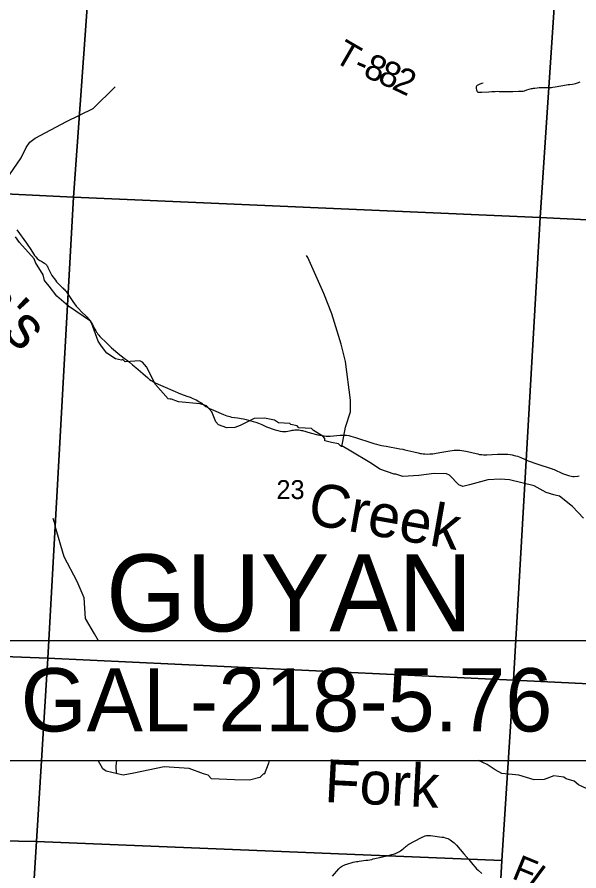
# Model space of a CAD drawing. Extents: x -2.1 to 31.9, y 6.3 to 28.3.
# Drawn here: x 1.321 to 2.564, y 23.525 to 25.414 of the extents above; entities that cross this region are included whole.
import ezdxf

# ---------------------------------------------------------------- set-up
doc = ezdxf.new("R2010")
doc.units = 0
for name, color, linetype in [('GM_X_County_Road', 7, 'Continuous'), ('GM_X_Minor_River', 7, 'Continuous'), ('GM_X_Minor_River_Text', 7, 'Continuous'), ('GM_X_Section', 7, 'Continuous'), ('GM_X_Section_Text', 7, 'Continuous'), ('GM_X_Township_Road', 7, 'Continuous'), ('GM_X_Township_Road_Text', 7, 'Continuous'), ('GM_X_Township_Text', 7, 'Continuous'), ('TX_P_1', 7, 'Continuous')]:
    doc.layers.add(name, color=color, linetype=linetype)

msp = doc.modelspace()

# ---------------------------------------------------------------- linework, layer by layer
at = {"layer": 'GM_X_County_Road'}
for points in [[(1.3205, 24.9435), (1.3263, 24.9353), (1.3361, 24.9224), (1.3423, 24.9139), (1.3465, 24.9078), (1.3488, 24.9043), (1.3513, 24.9004), (1.3572, 24.8904), (1.3596, 24.8868), (1.3624, 24.8835), (1.3654, 24.8805), (1.3693, 24.8775), (1.3718, 24.876)], [(1.3718, 24.876), (1.3735, 24.8749), (1.3783, 24.8721), (1.3818, 24.8698), (1.3832, 24.8687), (1.3845, 24.8677), (1.386, 24.8663), (1.3871, 24.8649), (1.3881, 24.8633), (1.3889, 24.8618), (1.3895, 24.8603), (1.3902, 24.8588), (1.3948, 24.8483), (1.3964, 24.8454), (1.3984, 24.8422), (1.4061, 24.8319), (1.4087, 24.8288), (1.4119, 24.8252), (1.4189, 24.8183), (1.421, 24.8162), (1.4228, 24.8145), (1.4248, 24.8125), (1.4267, 24.8105), (1.4282, 24.8087), (1.4298, 24.8068), (1.4314, 24.8047), (1.433, 24.8024), (1.4386, 24.7936), (1.4443, 24.785), (1.4522, 24.7748), (1.4543, 24.7722), (1.457, 24.7693), (1.4637, 24.7622), (1.474, 24.7525), (1.4762, 24.7504), (1.478, 24.7483), (1.48, 24.746), (1.4816, 24.744), (1.4831, 24.742), (1.4844, 24.74), (1.4856, 24.7383), (1.4867, 24.7365), (1.4878, 24.7345), (1.4889, 24.7325), (1.4933, 24.7238), (1.4954, 24.7201), (1.497, 24.7173), (1.4982, 24.7155), (1.5001, 24.7129), (1.5021, 24.7104), (1.5043, 24.7077), (1.5079, 24.7041), (1.5161, 24.6963), (1.5303, 24.6823), (1.5485, 24.6669), (1.561, 24.6577), (1.5654, 24.6543), (1.5701, 24.6505), (1.5767, 24.645), (1.5839, 24.6391), (1.5995, 24.626), (1.6106, 24.6158), (1.6143, 24.6128), (1.6175, 24.6106), (1.6209, 24.6085), (1.6251, 24.6061), (1.6334, 24.6024), (1.6488, 24.5954), (1.6657, 24.588), (1.6829, 24.5809), (1.6966, 24.5758), (1.7038, 24.5732), (1.7099, 24.5708), (1.7137, 24.5692), (1.7172, 24.5675), (1.7209, 24.5655), (1.7243, 24.5634), (1.7274, 24.5614), (1.7304, 24.5592), (1.7349, 24.5558), (1.739, 24.5531), (1.7428, 24.551), (1.7472, 24.5486), (1.7561, 24.5444), (1.778, 24.5348), (1.7819, 24.5333), (1.7856, 24.532), (1.7888, 24.531), (1.792, 24.5303), (1.7956, 24.5295), (1.8087, 24.5276), (1.8131, 24.527), (1.8169, 24.5264), (1.8222, 24.5255), (1.828, 24.5242), (1.8381, 24.5213), (1.8436, 24.5197), (1.8492, 24.5179), (1.8552, 24.5156), (1.8624, 24.5126), (1.8732, 24.5079), (1.8796, 24.5053), (1.8853, 24.5032), (1.8918, 24.5011), (1.8981, 24.4993), (1.9031, 24.4983), (1.9081, 24.4976), (1.9127, 24.4973), (1.9168, 24.4976), (1.9203, 24.4981), (1.9275, 24.4997), (1.9299, 24.5002), (1.9327, 24.5007), (1.9356, 24.5009), (1.9384, 24.5011), (1.9413, 24.5011), (1.9445, 24.5009), (1.9477, 24.5006), (1.9505, 24.5), (1.9527, 24.4994), (1.9698, 24.4945), (1.9864, 24.4901), (1.9955, 24.4883), (2.0003, 24.4875), (2.005, 24.4871), (2.0098, 24.4868), (2.0139, 24.487), (2.0361, 24.4893), (2.0406, 24.4895), (2.0455, 24.4893), (2.0503, 24.489), (2.055, 24.4884), (2.0598, 24.4874), (2.0648, 24.486), (2.0702, 24.4842), (2.1057, 24.4725), (2.1105, 24.471), (2.1162, 24.4693), (2.1216, 24.468), (2.1271, 24.4668), (2.1377, 24.4647), (2.1681, 24.4594), (2.1745, 24.4583), (2.1792, 24.4572), (2.199, 24.4521), (2.2088, 24.4499), (2.2127, 24.4491), (2.2162, 24.4486), (2.2196, 24.4482), (2.2234, 24.4478), (2.2285, 24.4475), (2.2342, 24.4478), (2.2378, 24.448), (2.2412, 24.4483), (2.2447, 24.4488), (2.2484, 24.4493), (2.2525, 24.45), (2.2564, 24.4507), (2.2784, 24.4546), (2.284, 24.4554), (2.2885, 24.4558), (2.2929, 24.456), (2.2972, 24.456), (2.3007, 24.4558), (2.3052, 24.4555), (2.3096, 24.455), (2.3139, 24.4542), (2.3179, 24.4534), (2.3365, 24.4486), (2.3405, 24.4477), (2.3444, 24.4469), (2.3491, 24.4462), (2.3533, 24.4458), (2.3565, 24.4457), (2.3602, 24.4458), (2.3841, 24.4471), (2.393, 24.4474), (2.3977, 24.4475), (2.4025, 24.4474), (2.4072, 24.4471), (2.412, 24.4466), (2.4164, 24.4458), (2.421, 24.4447), (2.4245, 24.4438), (2.4283, 24.4426), (2.4322, 24.4411), (2.4358, 24.4396), (2.452, 24.4327), (2.471, 24.4257), (2.5046, 24.415), (2.5067, 24.4142), (2.5093, 24.4132), (2.528, 24.4047), (2.5323, 24.403), (2.5364, 24.4013), (2.5408, 24.3999), (2.5443, 24.399), (2.5477, 24.3984), (2.5509, 24.3982), (2.5538, 24.3982), (2.5618, 24.3989), (2.5645, 24.3992)]]:
    msp.add_lwpolyline(points, dxfattribs=at)
at = {"layer": 'GM_X_Minor_River'}
for points in [[(1.2523, 24.9999), (1.2865, 25.0391), (1.3305, 25.1031), (1.341, 25.1256), (1.3496, 25.1374), (1.3609, 25.1462), (1.4305, 25.183), (1.4892, 25.2118), (1.5379, 25.2599)], [(2.5746, 24.306), (2.55, 24.3314), (2.5212, 24.3546), (2.5118, 24.3564), (2.5084, 24.3576), (2.4917, 24.3625), (2.4649, 24.3772), (2.4108, 24.3908), (2.3896, 24.3922), (2.3628, 24.3903), (2.322, 24.3791), (2.3076, 24.3761), (2.2982, 24.3795), (2.2781, 24.4007), (2.2709, 24.4037), (2.2441, 24.4048), (2.2097, 24.3998), (2.1745, 24.3981), (2.1594, 24.4031), (2.1556, 24.403), (2.1239, 24.4144), (2.105, 24.4265), (2.0562, 24.4564), (2.0384, 24.4666), (2.0373, 24.4647), (2.032, 24.4704), (2.0165, 24.473), (2.0017, 24.4771), (2.0021, 24.4817), (1.9979, 24.4874), (1.9767, 24.4999), (1.9722, 24.5044), (1.9446, 24.5055), (1.9408, 24.51), (1.9268, 24.513), (1.9249, 24.5153), (1.8996, 24.5168), (1.8909, 24.5225), (1.8686, 24.5266), (1.8455, 24.5261), (1.8146, 24.5105), (1.8032, 24.5066), (1.7851, 24.5058), (1.7669, 24.5119), (1.7609, 24.5191), (1.7522, 24.5411), (1.7404, 24.554), (1.7264, 24.5589), (1.6781, 24.5633), (1.6629, 24.5686), (1.6599, 24.5686), (1.6557, 24.5697), (1.6277, 24.6016), (1.6073, 24.6407), (1.599, 24.6509), (1.5925, 24.6539), (1.5604, 24.6516), (1.5555, 24.6565), (1.5525, 24.6554), (1.5392, 24.658), (1.5196, 24.6705), (1.5082, 24.6864), (1.5006, 24.6974), (1.4855, 24.738), (1.4836, 24.7415), (1.4352, 24.7748), (1.4091, 24.7968), (1.392, 24.8188), (1.3818, 24.8313), (1.3792, 24.8438), (1.3617, 24.8715), (1.3591, 24.8791), (1.3266, 24.9155), (1.3175, 24.928)], [(2.04, 24.4637), (2.0481, 24.5067), (2.0586, 24.5413), (2.0586, 24.5668), (2.0476, 24.6525), (2.0382, 24.6908), (2.0175, 24.7579), (1.9996, 24.8029), (1.9642, 24.8822), (1.9613, 24.8869)], [(1.5014, 24.0345), (1.4922, 24.0497), (1.4724, 24.0837), (1.4697, 24.1294), (1.4545, 24.1656), (1.4256, 24.22), (1.4057, 24.2878), (1.4044, 24.294), (1.4009, 24.3051)], [(1.8792, 23.7698), (1.8772, 23.7635), (1.8765, 23.7616), (1.8678, 23.7383), (1.8671, 23.7406), (1.8584, 23.7319), (1.8353, 23.7257), (1.8024, 23.7268), (1.7514, 23.7289), (1.7438, 23.7373), (1.7336, 23.7399), (1.7022, 23.752), (1.6467, 23.7556), (1.5794, 23.7418), (1.5556, 23.7371), (1.5182, 23.7458), (1.5159, 23.7473), (1.5106, 23.7511), (1.5004, 23.7697), (1.5003, 23.7698)], [(1.5408, 23.7414), (1.5404, 23.7569), (1.5417, 23.7698)], [(2.5838, 23.706), (2.563, 23.7154), (2.5539, 23.7238), (2.5362, 23.729), (2.5335, 23.7302), (2.5305, 23.7328), (2.5086, 23.7354), (2.4874, 23.7274), (2.4651, 23.727), (2.4311, 23.7371), (2.3936, 23.7405), (2.3785, 23.7492), (2.3611, 23.7609), (2.3421, 23.7698)]]:
    msp.add_lwpolyline(points, dxfattribs=at)
at = {"layer": 'GM_X_Section'}
for points in [[(0.4693, 26.1002), (1.5197, 26.0415), (1.4457, 25.016), (0.4184, 25.0658)], [(1.5197, 26.0415), (2.5466, 25.9887), (2.4786, 24.9709), (1.4457, 25.016)], [(2.5466, 25.9887), (3.6038, 25.9379), (3.5328, 24.9185), (2.4786, 24.9709)], [(0.4184, 25.0658), (1.4457, 25.016), (1.3895, 23.996), (0.3588, 24.0351)], [(1.4457, 25.016), (2.4786, 24.9709), (2.4194, 23.947), (1.3895, 23.996)], [(2.4786, 24.9709), (3.5328, 24.9185), (3.4671, 23.8965), (2.4194, 23.947)], [(0.3588, 24.0351), (1.3895, 23.996), (1.3641, 23.5904), (0.3317, 23.6098)], [(1.3895, 23.996), (2.4194, 23.947), (2.3938, 23.5483), (1.3641, 23.5904)], [(2.4194, 23.947), (3.4671, 23.8965), (3.4412, 23.4777), (3.416, 23.0562), (3.4084, 22.8979), (2.8085, 22.9264), (2.3612, 22.9526), (2.3614, 22.9562), (2.3709, 23.1348), (2.3938, 23.5483)], [(1.3641, 23.5904), (1.3376, 23.1681), (0.3083, 23.1964), (0.3317, 23.6098)], [(1.3641, 23.5904), (2.3938, 23.5483), (2.3709, 23.1348), (1.3376, 23.1681)]]:
    msp.add_lwpolyline(points, close=True, dxfattribs=at)
at = {"layer": 'GM_X_Township_Road'}
for points in [[(2.3525, 25.2681), (2.3486, 25.267), (2.3437, 25.2652), (2.3389, 25.2626), (2.3376, 25.2615), (2.3371, 25.26), (2.3368, 25.2584), (2.337, 25.2559), (2.3376, 25.253), (2.3382, 25.2512), (2.3392, 25.2495), (2.3402, 25.2484), (2.3415, 25.2479), (2.3443, 25.2478), (2.3494, 25.248), (2.365, 25.2491), (2.3716, 25.2495), (2.379, 25.2499), (2.3836, 25.25), (2.3878, 25.2499), (2.3969, 25.2496), (2.4034, 25.2496), (2.409, 25.2496), (2.4181, 25.2498), (2.4302, 25.25), (2.4357, 25.2501), (2.438, 25.2502), (2.4407, 25.2506), (2.4436, 25.2513), (2.4487, 25.253), (2.4595, 25.2559), (2.4617, 25.2564), (2.4639, 25.2568), (2.4669, 25.2572), (2.4718, 25.2579), (2.4762, 25.2583), (2.4807, 25.2586), (2.485, 25.2586), (2.4913, 25.2584), (2.4958, 25.2583), (2.4999, 25.2585), (2.5032, 25.2587), (2.5067, 25.2592), (2.5113, 25.26), (2.5364, 25.2643), (2.5401, 25.2649), (2.5438, 25.2653), (2.55, 25.266), (2.5533, 25.2665), (2.5563, 25.2671), (2.5586, 25.2677), (2.5608, 25.2685), (2.5666, 25.2708)], [(2.0191, 23.514), (2.0328, 23.5299), (2.0345, 23.5317), (2.0365, 23.5336), (2.0386, 23.5352), (2.0414, 23.5368), (2.0446, 23.5382), (2.0478, 23.5394), (2.0509, 23.5404), (2.0648, 23.5443), (2.0687, 23.5452), (2.0721, 23.5459), (2.0751, 23.5465), (2.0783, 23.5469), (2.0931, 23.5488), (2.0974, 23.5494), (2.1013, 23.5501), (2.1057, 23.5509), (2.109, 23.5517), (2.1123, 23.5528), (2.1158, 23.5536), (2.1198, 23.5546), (2.1394, 23.5586), (2.1451, 23.5599), (2.1501, 23.5613), (2.1542, 23.5625), (2.1582, 23.564), (2.1615, 23.5652), (2.1645, 23.5666), (2.1671, 23.5681), (2.1697, 23.5698), (2.1724, 23.5718), (2.1751, 23.5741), (2.1774, 23.5761), (2.1798, 23.5782), (2.1819, 23.58), (2.1839, 23.5816), (2.186, 23.5829), (2.1881, 23.5842), (2.2004, 23.5914), (2.2157, 23.5992), (2.2186, 23.6006), (2.2213, 23.6017), (2.2243, 23.6027), (2.2273, 23.6033), (2.2301, 23.6037), (2.2329, 23.6036), (2.2356, 23.6033), (2.2607, 23.6001), (2.2642, 23.5996), (2.2679, 23.5988), (2.2711, 23.598), (2.274, 23.5968), (2.277, 23.5953), (2.2795, 23.5938), (2.282, 23.5921), (2.2853, 23.5895), (2.2879, 23.5874), (2.2898, 23.5857), (2.2916, 23.5839), (2.2932, 23.5823), (2.3094, 23.5633), (2.3209, 23.5503), (2.3297, 23.5395), (2.3345, 23.5338), (2.3379, 23.5302), (2.3411, 23.5269), (2.3494, 23.5197)]]:
    msp.add_lwpolyline(points, dxfattribs=at)
at = {"layer": 'TX_P_1'}
msp.add_lwpolyline([(1.2977, 23.7698), (2.6072, 23.7698), (2.6072, 24.0345), (1.2977, 24.0345)], close=True, dxfattribs=at)

# ---------------------------------------------------------------- texts
at = {"layer": 'GM_X_Minor_River_Text'}
for s, rotation, p in [("John's", 315.0035, (1.0755, 24.927)), ('Creek', 350.0126, (1.9607, 24.2936)), ('Fork', 357.013, (1.9999, 23.678))]:
    msp.add_text(s, height=0.09469, rotation=rotation, dxfattribs=at).set_placement(p)
at = {"layer": 'GM_X_Section_Text'}
msp.add_text('23', height=0.04186, rotation=0, dxfattribs=at).set_placement((1.8949, 24.348))
at = {"layer": 'GM_X_Township_Road_Text'}
for s, rotation, p in [('T', 329.8543, (2.0193, 25.3178)), ('8', 336.7416, (2.0844, 25.284)), ('-', 337.0685, (2.063, 25.293)), ('8', 336.3405, (2.1165, 25.2702)), ('2', 334.5195, (2.1481, 25.2563)), ('F', 337.6802, (2.4134, 23.5096)), ('I', 323.4986, (2.4456, 23.4968))]:
    msp.add_text(s, height=0.0568, rotation=rotation, dxfattribs=at).set_placement(p)
at = {"layer": 'GM_X_Township_Text'}
msp.add_text('GUYAN', height=0.17045, rotation=0, dxfattribs=at).set_placement((1.5181, 24.0552))
at = {"layer": 'TX_P_1'}
msp.add_text('GAL-218-5.76', height=0.14, dxfattribs=at).set_placement((1.3293, 23.8338))

doc.saveas('drawing.dxf')
